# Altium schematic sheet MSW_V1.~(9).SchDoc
size B; Organization: ORGANIZATION; Address1: ADDRESS 1; Address2: ADDRESS 2; Address3: ADDRESS 3; Address4: ADDRESS 4; Revision: -; SheetNumber: 1; SheetTotal: 1; ENG_APP_DATE: --/--/--; DSN_APP_DATE: --/--/--; CHK_APP_DATE: --/--/--
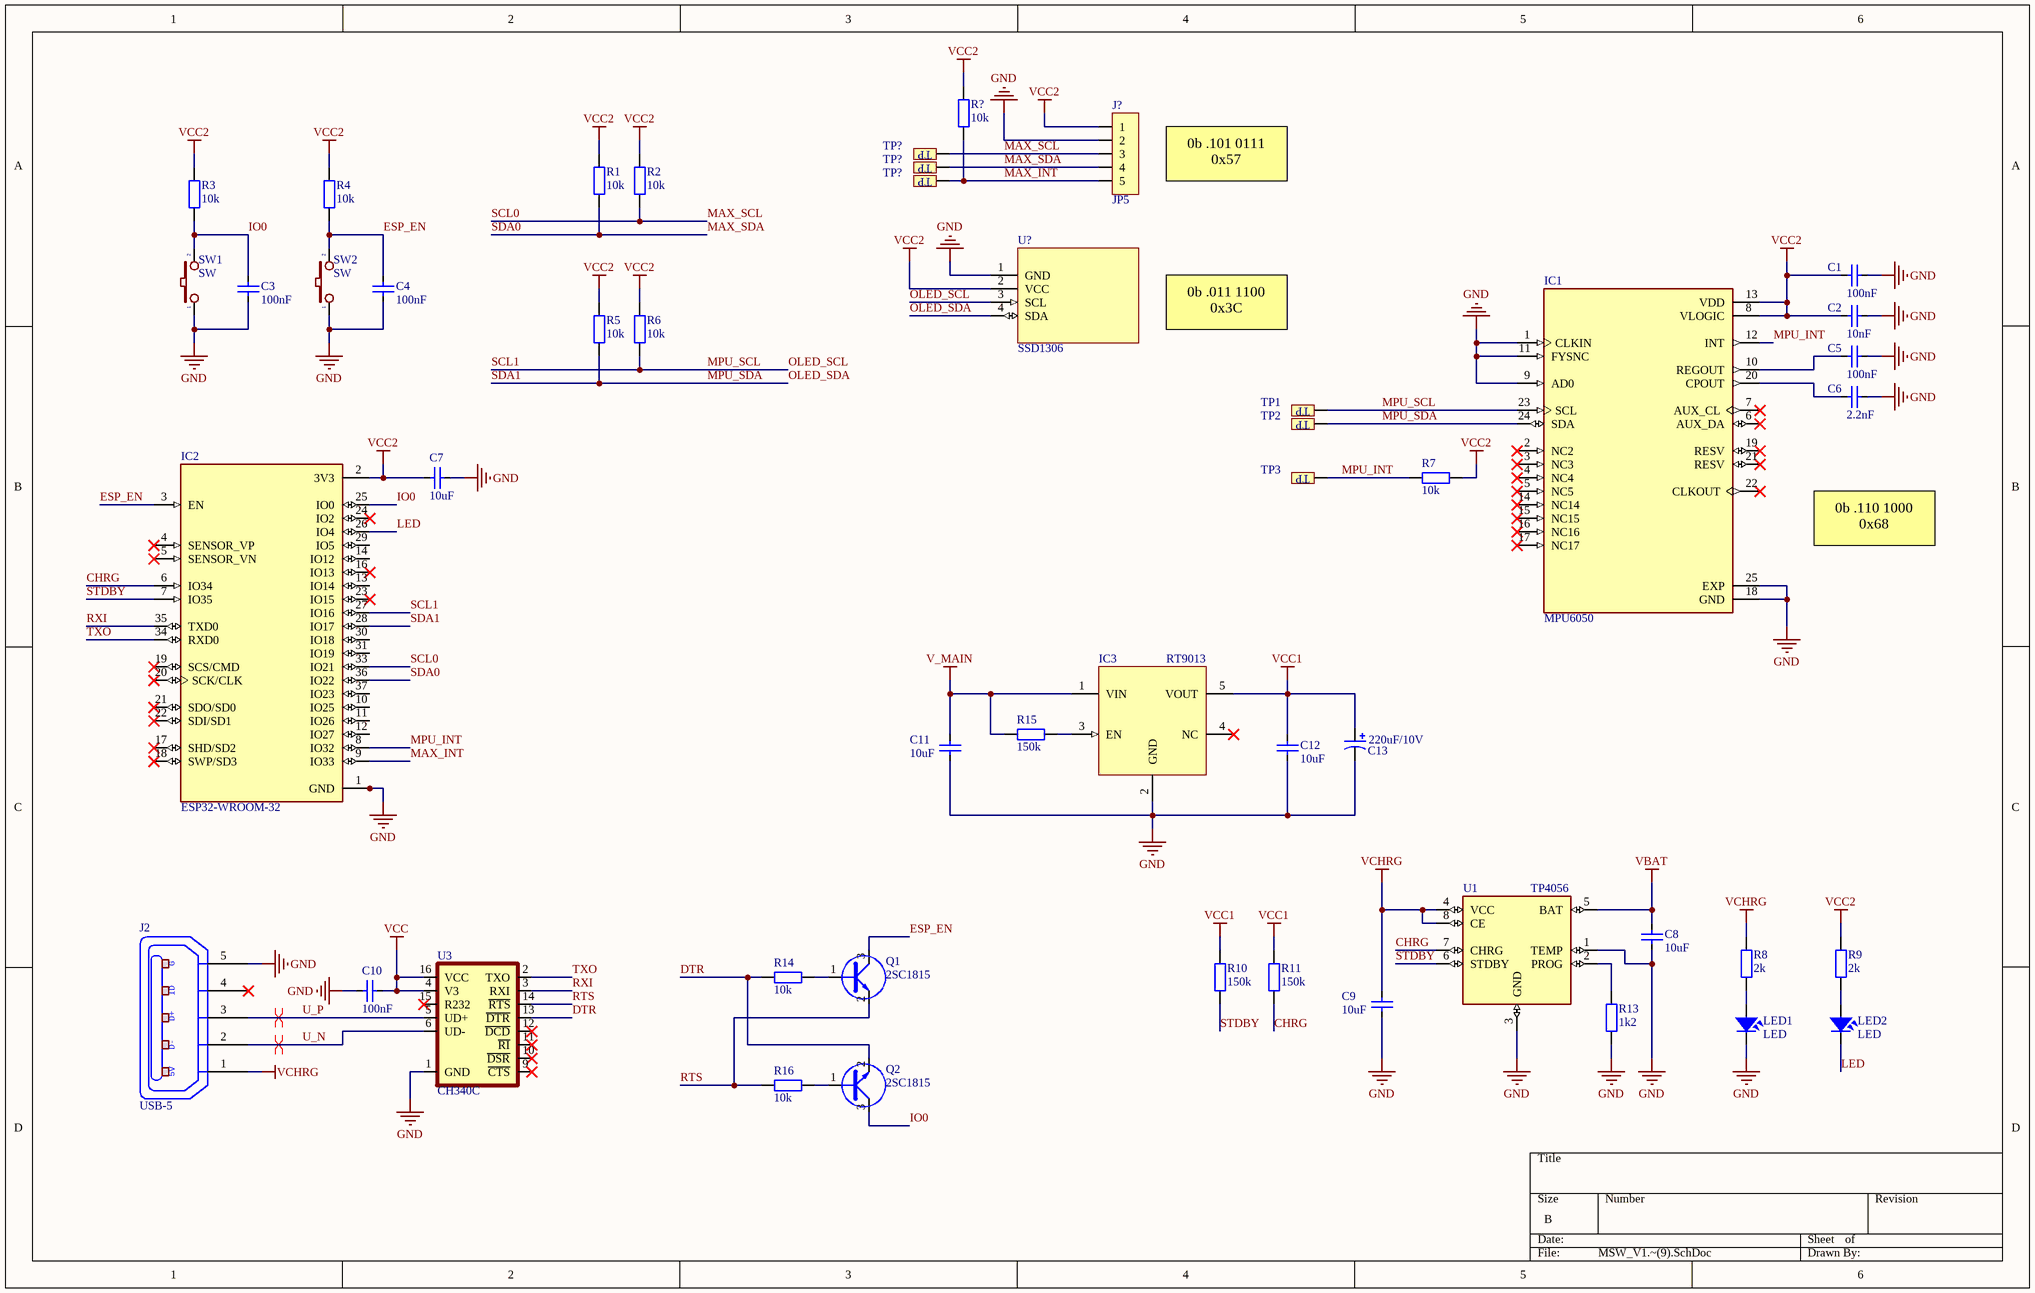
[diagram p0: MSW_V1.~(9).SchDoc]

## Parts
(Parts that share a designator on the sheet are numbered #1, #2 ... from top to bottom, then left to right.)
C1  100nF  [CAP_0603]
C2  10nF  [CAP_0603]
C3  100nF  [CAP_0603]
C4  100nF  [CAP_0603]
C5  100nF  [CAP_0603]
C6  2.2nF  [CAP_0603]
C7  10uF  [CAP_0603]
C8  10uF  [CAP_0603]
C9  10uF  [CAP_0603]
C10  100nF  [CAP_0603]
C11  10uF  [CAP_0603]
C12  10uF  [CAP_0603]
C13  220uF/10V  [CAP_7343]
IC1  MPU6050  [QFN24]
IC2  ESP32-WROOM-32  [MODULE_ESP32-WROOM-32]
IC3  RT9013  [SOT23-5]
J2  USB-5  [USB-M1]
J?  JP5  [Header5 - TH - 1.25MM]
LED1  LED  [LED-0805-Red]
LED2  LED  [LED-1206-Blue]
Q1  2SC1815  [SOT23D]
Q2  2SC1815  [SOT23D]
R1  10k  [RES-SMD-0603]
R2  10k  [RES-SMD-0603]
R3  10k  [RES-SMD-0603]
R4  10k  [RES-SMD-0603]
R5  10k  [RES-SMD-0603]
R6  10k  [RES-SMD-0603]
R7  10k  [RES-SMD-0603]
R8  2k  [RES-SMD-0603]
R9  2k  [RES-SMD-0603]
R10  150k  [RES-SMD-0603]
R11  150k  [RES-SMD-0603]
R13  1k2  [RES-SMD-0603]
R14  10k  [RES-SMD-0603]
R15  150k  [RES-SMD-0603]
R16  10k  [RES-SMD-0603]
R?  10k  [RES-SMD-0603]
SW1  SW  [SW 3x2x4]
SW2  SW  [SW 3x2x4]
TP1  TP  [TP_SMD]  (value not drawn)
TP2  TP  [TP_SMD]  (value not drawn)
TP3  TP  [TP_SMD]  (value not drawn)
TP?#1  TP  [TP_SMD]  (value not drawn)
TP?#2  TP  [TP_SMD]  (value not drawn)
TP?#3  TP  [TP_SMD]  (value not drawn)
U1  TP4056  [TP4056]
U3  CH340C  [SOP-16]
U?  SSD1306  [OLED 1.3 SSD1306 PRETTY NON POLE]

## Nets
GND: C1.1 C2.1 C3.2 C4.2 C5.1 C6.1 C7.2 C8.1 C9.1 C10.1 C11.1 C12.1 C13.2 IC1.1(CLKIN) IC1.9(AD0) IC1.11(FYSNC) IC1.18(GND) IC1.25(EXP) IC2.1(GND) IC2.15(GND) IC2.38(GND) IC2.39_1(GND) IC2.39_2(GND) IC2.39_3(GND) IC2.39_4(GND) IC2.39_5(GND) IC2.39_6(GND) IC2.39_7(GND) IC2.39_8(GND) IC2.39_9(GND) IC2.39_10(GND) IC2.39_11(GND) IC2.39_12(GND) IC2.39_13(GND) IC2.39_14(GND) IC2.39_15(GND) IC2.39_16(GND) IC2.39_17(GND) IC2.39_18(GND) IC2.39_19(GND) IC2.39_20(GND) IC2.39_21(GND) IC3.2(GND) J2.5(P5) J?.2 LED1.2 R13.1 SW1.1 SW2.1 U1.1(TEMP) U1.3(GND) U3.1(GND) U?.1(GND)
V_MAIN: C11.2 IC3.1(VIN) R15.1
VBAT: C8.2 U1.5(BAT)
VCC: C10.2 U3.4(V3) U3.16(VCC)
VCC1: C12.2 C13.1 IC3.5(VOUT) R10.1 R11.1
VCC2: C1.2 C2.2 C7.1 IC1.8(VLOGIC) IC1.13(VDD) IC2.2(3V3) J?.1 R1.2 R2.2 R3.2 R4.2 R5.2 R6.2 R7.1 R9.2 R?.1 U?.2(VCC)
VCHRG: C9.2 J2.1(P1) R8.2 U1.4(VCC) U1.8(CE)
CHRG: IC2.6(IO34) R11.2 U1.7(CHRG)
DTR: Q2.2(E) R14.2 U3.13(~{DTR})
ESP_EN: C4.1 IC2.3(EN) Q1.3(C) R4.1 SW2.2
IO0: C3.1 IC2.25(IO0) Q2.3(C) R3.1 SW1.2
LED: IC2.26(IO4) LED2.2
MAX_INT: IC2.9(IO33) J?.5 R?.2 TP?#3.1
MAX_SCL: IC2.33(IO21) J?.3 R2.1 TP?#1.1  [also labelled SCL0]
MAX_SDA: IC2.36(IO22) J?.4 R1.1 TP?#2.1  [also labelled SDA0]
MPU_INT: IC1.12(INT) IC2.8(IO32) R7.2 TP3.1
MPU_SCL: IC1.23(SCL) IC2.27(IO16) R6.1 TP1.1 U?.3(SCL)  [also labelled OLED_SCL, SCL1]
MPU_SDA: IC1.24(SDA) IC2.28(IO17) R5.1 TP2.1 U?.4(SDA)  [also labelled OLED_SDA, SDA1]
RTS: Q1.2(E) R16.2 U3.14(~{RTS})
RXI: IC2.35(TXD0) U3.3(RXI)
STDBY: IC2.7(IO35) R10.2 U1.6(STDBY)
TXO: IC2.34(RXD0) U3.2(TXO)
U_N: J2.2(P2) U3.6(UD-)
U_P: J2.3(P3) U3.5(UD+)
NetC5_2: C5.2 IC1.10(REGOUT)
NetC6_2: C6.2 IC1.20(CPOUT)
NetIC3_3: IC3.3(EN) R15.2
NetLED1_1: LED1.1 R8.1
NetLED2_1: LED2.1 R9.1
NetQ1_1: Q1.1(B) R14.1
NetQ2_1: Q2.1(B) R16.1
NetR13_2: R13.2 U1.2(PROG)

Not connected (* = marked no-connect by the designer): IC1 2(NC2)* 3(NC3)* 4(NC4)* 5(NC5)* 6(AUX_DA)* 7(AUX_CL)* 14(NC14)* 15(NC15)* 16(NC16)* 17(NC17)* 19(RESV)* 21(RESV)* 22(CLKOUT)*; IC2 4(SENSOR_VP)* 5(SENSOR_VN)* 10(IO25) 11(IO26) 12(IO27) 13(IO14) 14(IO12) 16(IO13)* 17(SHD/SD2)* 18(SWP/SD3)* 19(SCS/CMD)* 20(SCK/CLK)* 21(SDO/SD0)* 22(SDI/SD1)* 23(IO15)* 24(IO2)* 29(IO5) 30(IO18) 31(IO19) 37(IO23); IC3 4(NC)*; J2 4(P4)*; U3 9(~{CTS})* 10(~{DSR})* 11(~{RI})* 12(~{DCD})* 15(R232)*

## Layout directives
differential pair: U_N, U_P

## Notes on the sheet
- 0b .101 0111
  0x57
- 0b .011 1100
  0x3C
- 0b .110 1000
  0x68

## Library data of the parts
C1-C12 = CapSMD: Capacitor; Value: 33p
C13 = CAP_TAN_SMD: Polazied Tantalum Capacitor
IC1 = MPU6050_Chip: 3-axis gyroscope, 3-axis accelerometer
IC2 = ESP32-WROOM-32: Bluetooth, WiFi Transceiver Module 2.4GHz ~ 2.5GHz Surface Mount; MF: Espressif Systems
IC3 = RT9013: RT9013-33GB IC REG LINEAR 3.3V 500mA SOT23-5
J2 = USB-5: Manufacturer: FCI; Manufacturer Part Number: 10118193-0001LF; Connector Type: USB - micro B; Number of Contacts: 5; Gender: Receptacle; Specifications: USB 2.0; .Creator: MM; .Checked PCB: RF
J? = JP5x1: WR-PHD 2.54 mm Angled Socket Header; Manufacturer: W¨¹rth Elektronik eiSos GmbH; partNo: 613005143121; ComponentLink1 Description: Manufacturer; ComponentLink2 Description: Datasheet; NoPins: 05
LED1 LED2 = LED: LED Single colour Green and Red; Value: LED 3 ly Single Colour
Q1 Q2 = C1815: NPN 600mW, ECB; Value: C1815
R1-R11 R13-R16 R? = Resistor - SMD: Resistor SMD; Manufacturer: Generic Components; Class: Passive
SW1 SW2 = SW2: Switch button 2 pin; Value: SW chip 2 pin
TP1-TP3 TP?#1-TP?#3 = TP: CONNECT 1
U1 = TP4056: Complete single cell Li-Ion battery with a constant current / constant voltage linear charger
U3 = CH340C: USB to serial chip CH340; MF: WCH
U? = OLED 1.3 SSD1306: OLED Display 1.3" SSD1306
